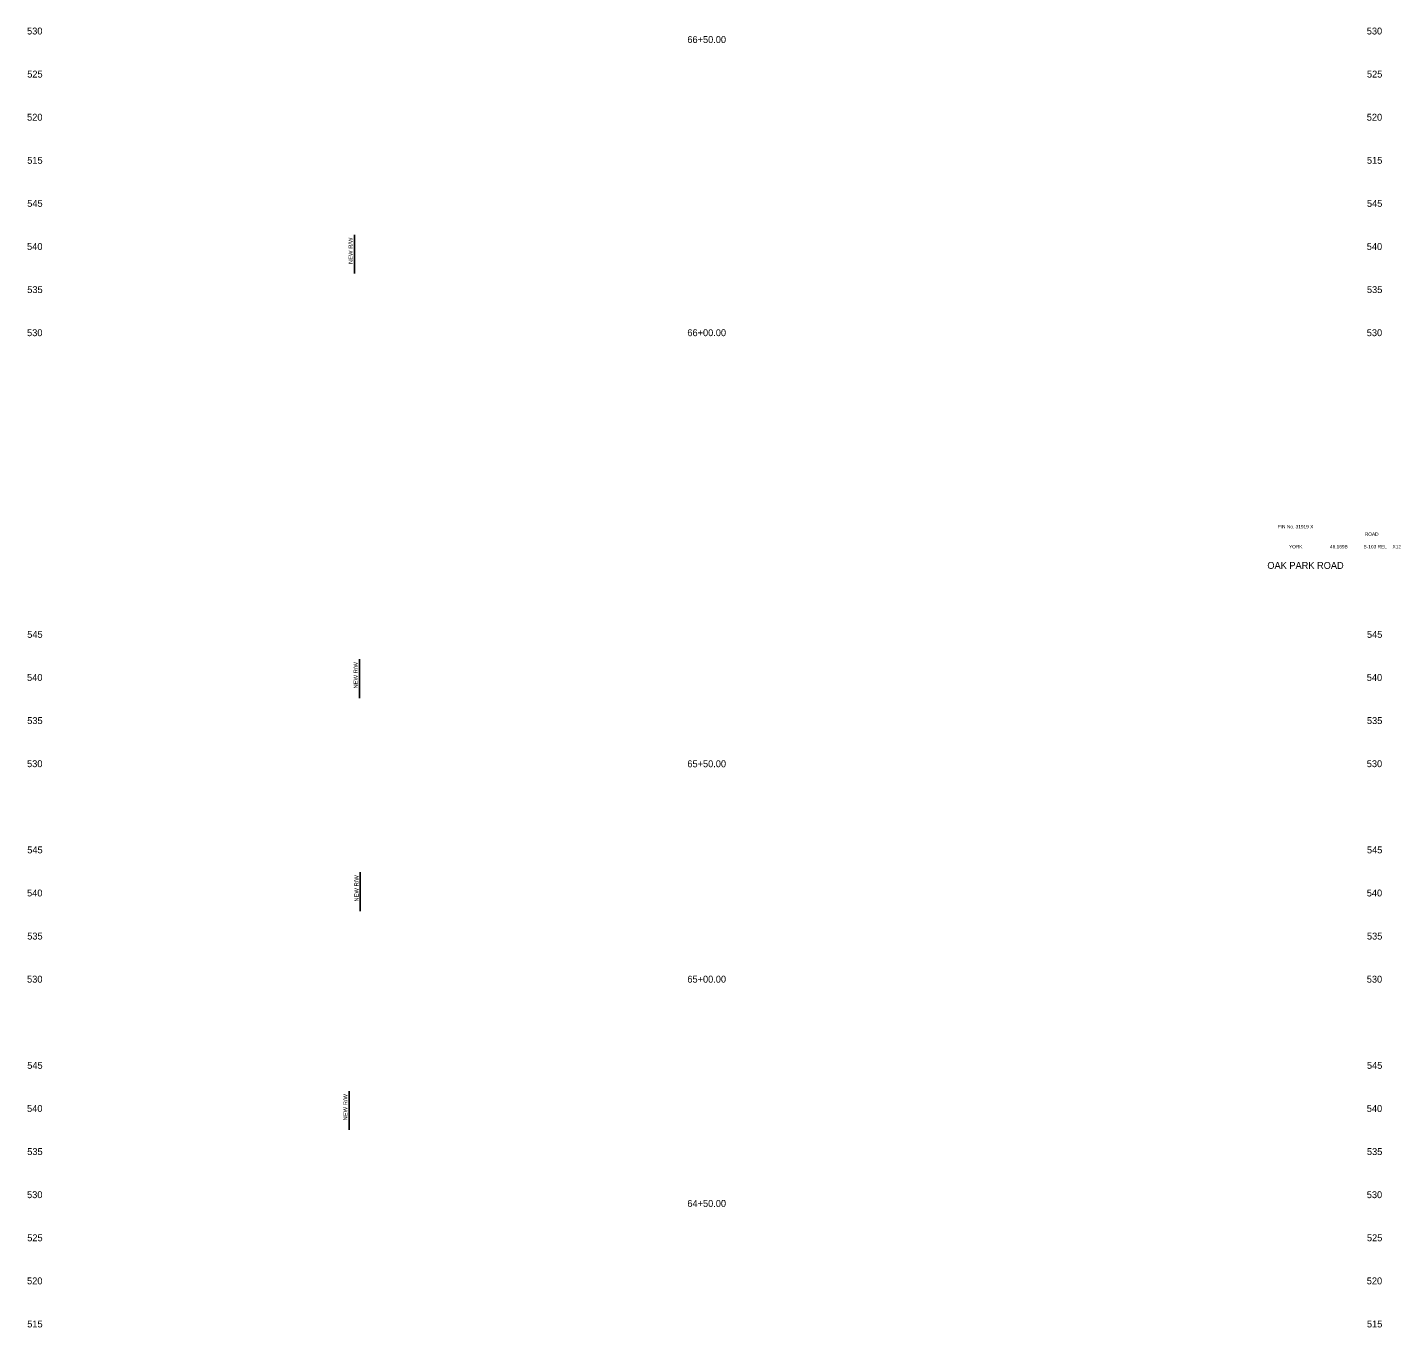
# Model space of a CAD drawing. Extents: x 1001 to 1161, y 1005 to 3518.
# Drawn here: x 1001.2 to 1160.6, y 2275.1 to 2425.9 of the extents above; entities that cross this region are included whole.
import ezdxf

# ---------------------------------------------------------------- set-up
doc = ezdxf.new("R2010")
doc.units = 0
for name, color, linetype in [('RD_SHT_TX', 7, 'Continuous'), ('RD_XS_NewRW', 7, 'Continuous'), ('RD_XS_TX_Elev_EX', 7, 'Continuous'), ('RD_XS_TX_Station', 7, 'Continuous')]:
    doc.layers.add(name, color=color, linetype=linetype)

msp = doc.modelspace()

# ---------------------------------------------------------------- linework, layer by layer
at = {"layer": 'RD_XS_NewRW'}
for p, q in [((1039.15, 2401.86), (1039.15, 2397.36)), ((1039.73, 2352.62), (1039.73, 2348.12)), ((1039.82, 2327.9), (1039.82, 2323.4)), ((1038.53, 2302.51), (1038.53, 2298.01))]:
    msp.add_line(p, q, dxfattribs=at)

# ---------------------------------------------------------------- texts
at = {"layer": 'RD_SHT_TX'}
for s, height, p in [('PIN No. 31919 X', 0.4, (1146.29, 2367.8)), ('ROAD', 0.4, (1156.41, 2366.93)), ('YORK', 0.4, (1147.61, 2365.48)), ('46.169B', 0.4, (1152.37, 2365.48)), ('S-103 REL', 0.4, (1156.26, 2365.48)), ('X12', 0.4, (1159.63, 2365.48)), ('OAK PARK ROAD', 0.8, (1145.1, 2363.1))]:
    msp.add_text(s, height=height, dxfattribs=at).set_placement(p)
at = {"layer": 'RD_XS_NewRW'}
for p in [(1038.94, 2398.47), (1039.53, 2349.22), (1039.62, 2324.5), (1038.33, 2299.11)]:
    msp.add_text('NEW R/W ', height=0.488, rotation=90, dxfattribs=at).set_placement(p)
at = {"layer": 'RD_XS_TX_Elev_EX'}
for s, p in [('530', (1001.14, 2425.1)), ('530', (1156.64, 2425.1)), ('525', (1001.16, 2420.1)), ('525', (1156.66, 2420.1)), ('520', (1001.14, 2415.1)), ('520', (1156.64, 2415.1)), ('515', (1001.16, 2410.1)), ('515', (1156.66, 2410.1)), ('545', (1001.16, 2405.1)), ('545', (1156.66, 2405.1)), ('540', (1001.14, 2400.1)), ('540', (1156.64, 2400.1)), ('535', (1001.16, 2395.1)), ('535', (1156.66, 2395.1)), ('530', (1001.14, 2390.1)), ('530', (1156.64, 2390.1)), ('545', (1001.16, 2355.1)), ('545', (1156.66, 2355.1)), ('540', (1001.14, 2350.1)), ('540', (1156.64, 2350.1)), ('535', (1001.16, 2345.1)), ('535', (1156.66, 2345.1)), ('530', (1001.14, 2340.1)), ('530', (1156.64, 2340.1)), ('545', (1001.16, 2330.1)), ('545', (1156.66, 2330.1)), ('540', (1001.14, 2325.1)), ('540', (1156.64, 2325.1)), ('535', (1001.16, 2320.1)), ('535', (1156.66, 2320.1)), ('530', (1001.14, 2315.1)), ('530', (1156.64, 2315.1)), ('545', (1001.16, 2305.1)), ('545', (1156.66, 2305.1)), ('540', (1001.14, 2300.1)), ('540', (1156.64, 2300.1)), ('535', (1001.16, 2295.1)), ('535', (1156.66, 2295.1)), ('530', (1001.14, 2290.1)), ('530', (1156.64, 2290.1)), ('525', (1001.16, 2285.1)), ('525', (1156.66, 2285.1)), ('520', (1001.14, 2280.1)), ('520', (1156.64, 2280.1)), ('515', (1001.16, 2275.1)), ('515', (1156.66, 2275.1))]:
    msp.add_text(s, height=0.8, dxfattribs=at).set_placement(p)
at = {"layer": 'RD_XS_TX_Station'}
for s, p in [('66+50.00', (1077.78, 2424.11)), ('66+00.00', (1077.78, 2390.1)), ('65+50.00', (1077.78, 2340.09)), ('65+00.00', (1077.78, 2315.1)), ('64+50.00', (1077.78, 2289.08))]:
    msp.add_text(s, height=0.8, dxfattribs=at).set_placement(p)

doc.saveas('drawing.dxf')
